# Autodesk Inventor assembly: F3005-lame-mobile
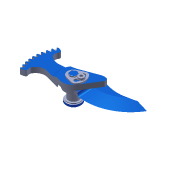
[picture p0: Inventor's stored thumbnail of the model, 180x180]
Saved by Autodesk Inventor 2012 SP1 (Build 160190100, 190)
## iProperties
Created: 2014-12
Part Number: F3005-lame-mobile
Document SubType Name: Assembly
Designer: Bruno
Mass: 16.4394 g
Surface Area: 115.66 cm^2
Volume: 16.4394 cm^3
Density: 1 g/cm^3
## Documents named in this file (8)
- D:\Cours\Systèmes\secateur-hydrogene-Pragma\Documentation\Dossier technique Infaco F3005\Solidworks\Composants importés\F3005-lame-mobile.iam
- D:\Cours\Systèmes\secateur-hydrogene-Pragma\Documentation\Dossier technique Infaco F3005\Solidworks\Composants importés\F3005\Coussinet lame_Cote mini.ipt
- D:\Cours\Systèmes\secateur-hydrogene-Pragma\Documentation\Dossier technique Infaco F3005\Solidworks\Composants importés\F3005\Axe lame_cote maxi.ipt
- D:\Cours\Systèmes\secateur-hydrogene-Pragma\Documentation\Dossier technique Infaco F3005\Solidworks\Composants importés\F3005\Lamelle blocage.ipt
- D:\Cours\Systèmes\secateur-hydrogene-Pragma\Documentation\Dossier technique Infaco F3005\Solidworks\Composants importés\F3005\Vis M4X8.ipt
- D:\Cours\Systèmes\secateur-hydrogene-Pragma\Documentation\Dossier technique Infaco F3005\Solidworks\Composants importés\F3005\Rondelles M4.ipt
- D:\Cours\Systèmes\secateur-hydrogene-Pragma\Documentation\Dossier technique Infaco F3005\Solidworks\Composants importés\F3005\Crémaillère_Taillage.ipt
- D:\Cours\Systèmes\secateur-hydrogene-Pragma\Documentation\Dossier technique Infaco F3005\Solidworks\Composants importés\F3005\Lame_cote mini.ipt
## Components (7 placed, 7 different names)
1. Coussinet lame_Cote mini:1
2. Axe lame_cote maxi:1
3. Lamelle blocage:1
4. Vis M4X8:1
5. Rondelles M4:1
6. Crémaillère_Taillage:1
7. Lame_cote mini:1
